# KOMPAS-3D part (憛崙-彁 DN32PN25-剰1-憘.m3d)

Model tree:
1. Объединить компоненты:1  (labels: СЕНС-ПР DN32PN25-ДП1)
2. Эскиз:1
3. Операция выдавливания:1
     Расстояние 1 = 14
4. Фаска:1
     Угол = 45; Длина 1 = 2; Длина 2 = 2

Referenced files in D:\Савин\!СЕНСОР\3D для заказчика\!Новый перечень\СЕНС-ПР\3. СЕНС-ПР-ДП\DN32\: СЕНС-ПР DN32PN25-ДП1.a3d
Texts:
  СЕНС-ПР DN32PN25-ДП1-СВ
  ООО НПП Сенсор
  СЕНС-ПР DN32PN25-ДП1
